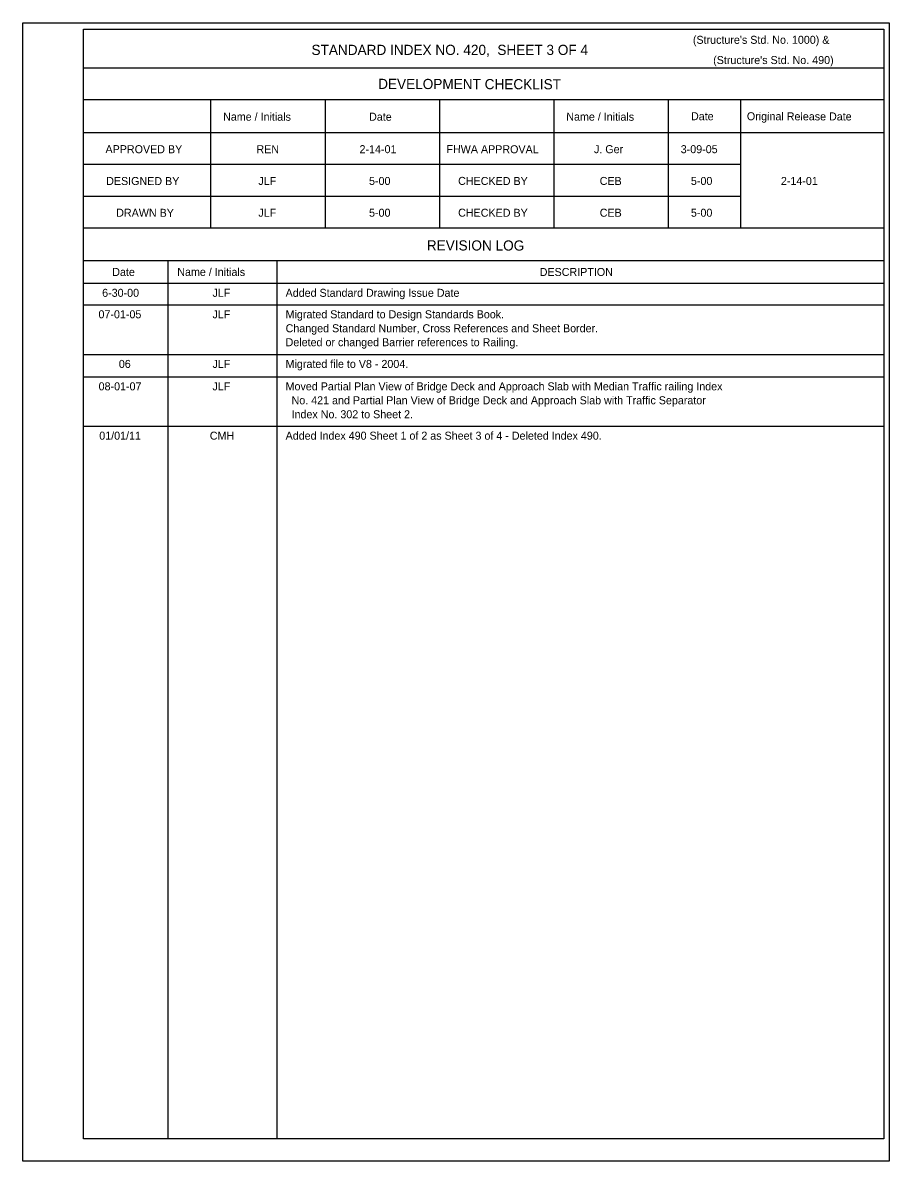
# Model space of a CAD drawing. Extents: x 122731 to 122840, y 88054 to 88118.
# Drawn here: x 122807.44 to 122840.16, y 88068.04 to 88111.04 of the extents above; entities that cross this region are included whole.
import ezdxf

# ---------------------------------------------------------------- set-up
doc = ezdxf.new("R2010")
doc.units = 0
for name, color, linetype in [('Border', 7, 'Continuous'), ('Dimension', 7, 'Continuous'), ('PlotBorder_dp', 7, 'Continuous'), ('TextStructures', 7, 'Continuous')]:
    doc.layers.add(name, color=color, linetype=linetype)

msp = doc.modelspace()

# ---------------------------------------------------------------- linework, layer by layer
at = {"layer": 'Border'}
for p, q in [((122839.957, 88109.33), (122809.736, 88109.33)), ((122839.957, 88108.13), (122809.736, 88108.13)), ((122814.536, 88108.13), (122814.536, 88103.288)), ((122818.856, 88108.13), (122818.856, 88103.288)), ((122823.176, 88108.13), (122823.176, 88103.288)), ((122827.496, 88108.13), (122827.496, 88103.288)), ((122831.816, 88108.13), (122831.816, 88103.288)), ((122834.539, 88108.13), (122834.539, 88103.288)), ((122839.957, 88106.888), (122809.736, 88106.888)), ((122834.539, 88105.688), (122809.736, 88105.688)), ((122834.539, 88104.488), (122809.736, 88104.488)), ((122839.957, 88103.288), (122809.736, 88103.288)), ((122839.957, 88102.047), (122809.736, 88102.047)), ((122812.917, 88102.047), (122812.917, 88068.887)), ((122817.03, 88102.047), (122817.03, 88068.887)), ((122839.957, 88101.201), (122809.736, 88101.201))]:
    msp.add_line(p, q, dxfattribs=at)
msp.add_lwpolyline([(122809.737, 88110.801), (122839.957, 88110.801), (122839.957, 88068.887), (122809.737, 88068.887)], close=True, dxfattribs=at)
at = {"layer": 'Dimension'}
for p, q in [((122809.737, 88100.39), (122839.957, 88100.39)), ((122809.737, 88098.515), (122839.957, 88098.515)), ((122809.737, 88097.669), (122839.957, 88097.669)), ((122809.737, 88095.805), (122839.957, 88095.805))]:
    msp.add_line(p, q, dxfattribs=at)
at = {"layer": 'PlotBorder_dp'}
msp.add_line((122807.441, 88068.045), (122807.441, 88068.045), dxfattribs=at)
msp.add_lwpolyline([(122807.441, 88111.045), (122840.161, 88111.045), (122840.161, 88068.045), (122807.441, 88068.045)], close=True, dxfattribs=at)

# ---------------------------------------------------------------- texts
at = {"layer": 'TextStructures'}
for s, height, p in [("(Structure's Std. No. 1000) &", 0.3024, (122832.746, 88110.25)), ('STANDARD INDEX NO. 420,  SHEET 3 OF 4', 0.384, (122818.343, 88109.829)), ("(Structure's Std. No. 490)", 0.3024, (122833.512, 88109.485)), ('REN', 0.3024, (122816.264, 88106.119)), ('2-14-01', 0.3024, (122820.158, 88106.119)), ('J. Ger', 0.3024, (122829.011, 88106.119)), ('3-09-05', 0.3024, (122832.287, 88106.119)), ('JLF', 0.3024, (122816.336, 88104.919)), ('5-00', 0.3024, (122820.517, 88104.919)), ('CEB', 0.3024, (122829.228, 88104.919)), ('5-00', 0.3024, (122832.672, 88104.919)), ('2-14-01', 0.3024, (122836.07, 88104.919)), ('JLF', 0.3024, (122816.336, 88103.719)), ('5-00', 0.3024, (122820.517, 88103.719)), ('CEB', 0.3024, (122829.228, 88103.719)), ('5-00', 0.3024, (122832.672, 88103.719)), ('DESCRIPTION', 0.3024, (122826.962, 88101.481)), ('6-30-00', 0.3024, (122810.438, 88100.694)), ('JLF', 0.3024, (122814.606, 88100.694)), ('Added Standard Drawing Issue Date', 0.3024, (122817.366, 88100.694)), ('07-01-05', 0.3024, (122810.3, 88099.883)), ('JLF', 0.3024, (122814.606, 88099.883)), ('Migrated Standard to Design Standards Book.', 0.3024, (122817.366, 88099.883)), ('Changed Standard Number, Cross References and Sheet Border.', 0.3024, (122817.366, 88099.355)), ('Deleted or changed Barrier references to Railing.', 0.3024, (122817.366, 88098.828)), ('06', 0.3024, (122811.068, 88098.008)), ('JLF', 0.3024, (122814.606, 88098.008)), ('Migrated file to V8 - 2004.', 0.3024, (122817.366, 88098.008)), ('08-01-07', 0.3024, (122810.305, 88097.162)), ('JLF', 0.3024, (122814.606, 88097.162)), ('Moved Partial Plan View of Bridge Deck and Approach Slab with Median Traffic railing Index ', 0.3024, (122817.366, 88097.162)), ('  No. 421 and Partial Plan View of Bridge Deck and Approach Slab with Traffic Separator ', 0.3024, (122817.366, 88096.635)), ('  Index No. 302 to Sheet 2.', 0.3024, (122817.366, 88096.107)), ('01/01/11', 0.3024, (122810.329, 88095.298)), ('CMH', 0.3024, (122814.504, 88095.298)), ('Added Index 490 Sheet 1 of 2 as Sheet 3 of 4 - Deleted Index 490.', 0.3024, (122817.366, 88095.298))]:
    msp.add_text(s, height=height, dxfattribs=at).set_placement(p)
for s, height, p in [('DEVELOPMENT CHECKLIST', 0.384, (122820.86, 88108.545)), ('Name / Initials', 0.3024, (122815.005, 88107.349)), ('Date', 0.3024, (122820.517, 88107.346)), ('Name / Initials', 0.3024, (122827.965, 88107.349)), ('Date', 0.3024, (122832.675, 88107.364)), ('Original Release Date', 0.3024, (122834.785, 88107.363)), ('APPROVED BY', 0.3024, (122810.564, 88106.121)), ('FHWA APPROVAL', 0.3024, (122823.439, 88106.121)), ('DESIGNED BY', 0.3024, (122810.589, 88104.919)), ('CHECKED BY', 0.3024, (122823.881, 88104.921)), ('DRAWN BY', 0.3024, (122810.969, 88103.719)), ('CHECKED BY', 0.3024, (122823.881, 88103.721)), ('REVISION LOG', 0.384, (122822.698, 88102.447)), ('Date', 0.3024, (122810.82, 88101.482)), ('Name / Initials', 0.3024, (122813.275, 88101.485))]:
    msp.add_text(s, height=height, rotation=359.8756, dxfattribs=at).set_placement(p)

doc.saveas('drawing.dxf')
